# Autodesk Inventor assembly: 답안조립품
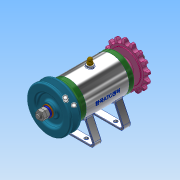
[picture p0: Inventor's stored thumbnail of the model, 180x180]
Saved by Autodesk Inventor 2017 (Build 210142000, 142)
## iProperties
Part Number: 답안조립품
Material: 일반
Document SubType Name: Assembly
Designer: Administrator
Author: Administrator
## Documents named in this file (16)
- C:\Users\Administrator\Desktop\711206V1004\답안조립품.iam
- C:\Users\Administrator\Desktop\711206V1004\본체.ipt
- C:\Users\Administrator\Desktop\711206V1004\711206V1004\V벨트풀리.ipt
- C:\Users\Administrator\Desktop\711206V1004\711206V1004\너트 M8.ipt
- C:\Users\Administrator\Desktop\711206V1004\711206V1004\니플 M6 x 0.75.ipt
- C:\Users\Administrator\Desktop\711206V1004\711206V1004\베어링 6002.ipt
- C:\Users\Administrator\Desktop\711206V1004\711206V1004\볼트 M4 x 12.ipt
- C:\Users\Administrator\Desktop\711206V1004\711206V1004\볼트 M6 x 8.ipt
- C:\Users\Administrator\Desktop\711206V1004\711206V1004\스프로킷.ipt
- C:\Users\Administrator\Desktop\711206V1004\711206V1004\스프링와셔 8.ipt
- C:\Users\Administrator\Desktop\711206V1004\711206V1004\오일 실 15 x 25 x 7.ipt
- C:\Users\Administrator\Desktop\711206V1004\711206V1004\와셔 6 x 11.5.ipt
- C:\Users\Administrator\Desktop\711206V1004\711206V1004\와셔 8 x 17.ipt
- C:\Users\Administrator\Desktop\711206V1004\711206V1004\축.ipt
- C:\Users\Administrator\Desktop\711206V1004\711206V1004\커버.ipt
- C:\Users\Administrator\Desktop\711206V1004\711206V1004\키 3 x 3.ipt
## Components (11 placed, 3 different names)
1. V벨트풀리:1
2. KS B 2023 6002 - 15 x 32 x 9:1
3. KS B 2023 6002 - 15 x 32 x 9:2
4. ISO 4762 M4 x 12:2
5. ISO 4762 M4 x 12:3
6. ISO 4762 M4 x 12:4
7. ISO 4762 M4 x 12:5
8. ISO 4762 M4 x 12:1
9. ISO 4762 M4 x 12:6
10. ISO 4762 M4 x 12:7
11. ISO 4762 M4 x 12:8
